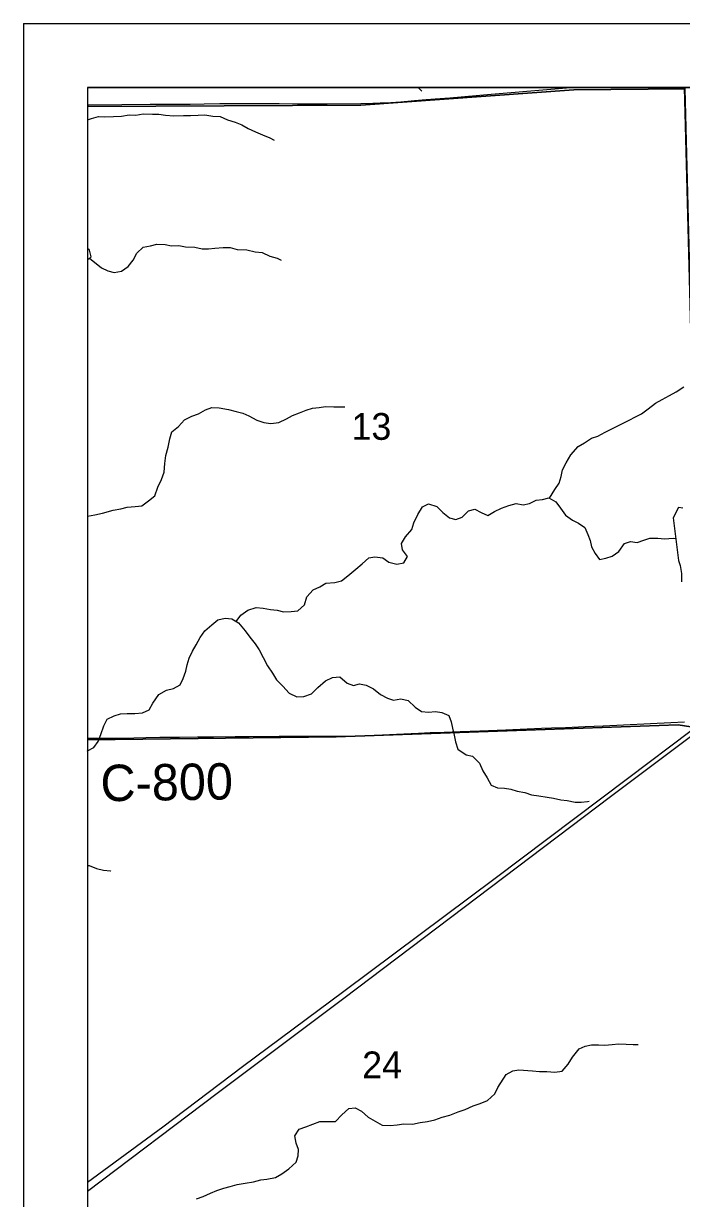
# Model space of a CAD drawing. Extents: x 0 to 34, y 0 to 22.
# Drawn here: x 2 to 3.028, y 19.165 to 21 of the extents above; entities that cross this region are included whole.
import ezdxf

# ---------------------------------------------------------------- set-up
doc = ezdxf.new("R2010")
doc.units = 0
for name, color, linetype in [('Default', 7, 'Continuous'), ('GM_X_County_Road', 7, 'Continuous'), ('GM_X_County_Road_Text', 7, 'Continuous'), ('GM_X_Interstate_Route', 7, 'Continuous'), ('GM_X_Minor_Lake', 7, 'Continuous'), ('GM_X_Minor_River', 7, 'Continuous'), ('GM_X_Rail_Line', 7, 'Continuous'), ('GM_X_Section_Text', 7, 'Continuous'), ('GM_X_Township_Road', 7, 'Continuous'), ('SH_Cut_Line', 7, 'Continuous'), ('SH_Data', 7, 'Continuous')]:
    doc.layers.add(name, color=color, linetype=linetype)

msp = doc.modelspace()

# ---------------------------------------------------------------- linework, layer by layer
at = {"layer": 'Default'}
for points in [[(3.0341, 20.9), (2.1, 20.9), (2.1, 20.8702), (2.5271, 20.8724), (2.8601, 20.8963), (3.0341, 20.898)], [(2.1, 20.8702), (2.1, 19.8813), (2.4888, 19.8857), (3.0228, 19.9046), (3.0592, 19.8987), (3.0341, 20.898), (2.8601, 20.8963), (2.5271, 20.8724)], [(2.1, 19.8813), (2.1, 18.8733), (3.073, 18.8909), (3.0592, 19.8987), (3.0228, 19.9046), (2.4888, 19.8857)]]:
    msp.add_lwpolyline(points, close=True, dxfattribs=at)
at = {"layer": 'GM_X_County_Road'}
msp.add_lwpolyline([(2.1, 19.8836), (2.1323, 19.8836), (2.1448, 19.8839), (2.1726, 19.8844), (2.1912, 19.8848), (2.213, 19.8852), (2.244, 19.8854), (2.272, 19.8857), (2.2968, 19.8859), (2.331, 19.8862), (2.3528, 19.8864), (2.3994, 19.8868), (2.4243, 19.8869), (2.4678, 19.887), (2.4989, 19.8866), (2.5176, 19.8867), (2.5331, 19.8874), (2.5611, 19.889), (2.5828, 19.89), (2.617, 19.8915), (2.6356, 19.8925), (2.6573, 19.8932), (2.6822, 19.894), (2.7133, 19.8951), (2.7536, 19.8968), (2.8095, 19.8992), (2.825, 19.8998), (2.8467, 19.9005), (2.8778, 19.9018), (2.9058, 19.903), (3.0114, 19.908), (3.0331, 19.909)], dxfattribs=at)
at = {"layer": 'GM_X_Interstate_Route'}
msp.add_lwpolyline([(3.0331, 20.9), (2.1, 20.9), (2.1, 16.8784), (2.6014, 16.878), (3.0939, 16.8719), (3.0724, 18.2926), (3.0747, 18.8969), (3.067, 19.3838), (3.0588, 19.9042)], close=True, dxfattribs=at)
at = {"layer": 'GM_X_Minor_Lake'}
for points in [[(2.1056, 20.6357), (2.1031, 20.646), (2.1, 20.6486)], [(2.1, 20.6315), (2.1017, 20.6323), (2.1041, 20.6339), (2.1056, 20.6357)]]:
    msp.add_lwpolyline(points, dxfattribs=at)
at = {"layer": 'GM_X_Minor_River'}
for points in [[(2.6166, 20.9), (2.6168, 20.8998), (2.6224, 20.8944)], [(2.1, 20.8493), (2.1063, 20.8516), (2.1173, 20.8549), (2.1272, 20.8544), (2.1404, 20.8547), (2.1533, 20.8553), (2.1651, 20.8571), (2.1753, 20.857), (2.1871, 20.8588), (2.2014, 20.8586), (2.2117, 20.8582), (2.2219, 20.8569), (2.2347, 20.8557), (2.2499, 20.8563), (2.2609, 20.8562), (2.273, 20.8568), (2.2836, 20.8571), (2.2957, 20.8551), (2.3074, 20.8546), (2.3187, 20.8495), (2.3308, 20.8456), (2.341, 20.8417), (2.3512, 20.8359), (2.3625, 20.8309), (2.3735, 20.8262), (2.3848, 20.8212), (2.3919, 20.8177)], [(2.1034, 20.6334), (2.1218, 20.6185), (2.132, 20.6138), (2.1418, 20.6111), (2.1532, 20.6129), (2.1634, 20.6203), (2.1715, 20.6305), (2.1769, 20.6411), (2.1872, 20.6505), (2.1982, 20.6526), (2.2084, 20.6552), (2.2213, 20.6547), (2.2315, 20.6527), (2.2429, 20.653), (2.2534, 20.651), (2.2675, 20.6508), (2.2792, 20.6481), (2.289, 20.648), (2.2989, 20.649), (2.3121, 20.65), (2.3231, 20.6499), (2.3341, 20.6471), (2.3488, 20.6462), (2.3621, 20.6431), (2.373, 20.6422), (2.3851, 20.6364), (2.3964, 20.6336), (2.4028, 20.6302)], [(2.8218, 20.2586), (2.83, 20.272), (2.8372, 20.2818), (2.84, 20.2924), (2.842, 20.303), (2.8477, 20.314), (2.855, 20.3264), (2.8665, 20.3392), (2.8764, 20.3452), (2.8874, 20.3523), (2.8973, 20.3552), (2.9091, 20.3619), (2.9224, 20.3686), (2.9331, 20.3735), (2.9464, 20.3805), (2.9563, 20.3854), (2.9658, 20.3902), (2.9761, 20.3981), (2.9875, 20.4067), (2.9982, 20.4127), (3.0092, 20.419), (3.0198, 20.4246), (3.0316, 20.4325)], [(2.1, 20.2305), (2.1117, 20.2323), (2.1234, 20.2352), (2.1401, 20.2396), (2.1519, 20.2418), (2.1618, 20.2444), (2.1743, 20.2454), (2.1849, 20.2468), (2.1952, 20.2543), (2.2051, 20.2621), (2.2101, 20.2758), (2.2159, 20.2875), (2.2198, 20.2992), (2.221, 20.3128), (2.2223, 20.325), (2.2258, 20.3382), (2.2286, 20.3511), (2.2317, 20.3621), (2.242, 20.3707), (2.2515, 20.3808), (2.2629, 20.3868), (2.2736, 20.3905), (2.2842, 20.3968), (2.2941, 20.4001), (2.3058, 20.3997), (2.3202, 20.3969), (2.3323, 20.3937), (2.3425, 20.3913), (2.3523, 20.3871), (2.3644, 20.3805), (2.3753, 20.377), (2.3867, 20.3753), (2.3988, 20.3767), (2.411, 20.3823), (2.4205, 20.3879), (2.4311, 20.3916), (2.4418, 20.3961), (2.4516, 20.399), (2.4622, 20.4004), (2.4717, 20.4015), (2.485, 20.401), (2.4959, 20.4012), (2.502, 20.4012)], [(2.3321, 20.066), (2.3398, 20.0757), (2.3505, 20.0836), (2.3634, 20.0876), (2.3744, 20.0867), (2.3861, 20.0847), (2.3963, 20.0839), (2.4061, 20.0811), (2.4182, 20.0818), (2.4285, 20.0824), (2.4392, 20.0918), (2.4427, 20.1047), (2.4526, 20.1152), (2.4629, 20.12), (2.4724, 20.1256), (2.4864, 20.127), (2.497, 20.1296), (2.507, 20.1374), (2.5195, 20.1476), (2.5291, 20.1562), (2.5394, 20.1656), (2.5492, 20.167), (2.5613, 20.1654), (2.5711, 20.1584), (2.5832, 20.1557), (2.5942, 20.1575), (2.6, 20.1676), (2.5921, 20.178), (2.5907, 20.1878), (2.5968, 20.198), (2.6068, 20.2097), (2.6099, 20.2199), (2.6164, 20.2331), (2.6234, 20.2448), (2.6329, 20.2497), (2.6457, 20.2457), (2.6551, 20.2362), (2.6656, 20.2277), (2.6755, 20.2253), (2.6857, 20.229), (2.6953, 20.2388), (2.7051, 20.2414), (2.7153, 20.236), (2.7255, 20.2313), (2.7361, 20.238), (2.7468, 20.2429), (2.7586, 20.2469), (2.7696, 20.2502), (2.7809, 20.2482), (2.7908, 20.2504), (2.801, 20.2552), (2.8109, 20.2563), (2.8208, 20.2592), (2.8317, 20.2527), (2.8392, 20.2427), (2.847, 20.232), (2.8576, 20.2243), (2.8674, 20.2197), (2.8772, 20.2128), (2.882, 20.2017), (2.8853, 20.1922), (2.8875, 20.1827), (2.8931, 20.1724), (2.8998, 20.1628), (2.9101, 20.165), (2.9196, 20.168), (2.9302, 20.1754), (2.9391, 20.1879), (2.9486, 20.1908), (2.9588, 20.1892), (2.9694, 20.1929), (2.9789, 20.1962), (2.991, 20.1961), (3.0016, 20.1952), (3.0149, 20.1959), (3.0191, 20.1956)], [(3.03, 20.2431), (3.0236, 20.244), (3.0151, 20.2281)], [(3.0151, 20.2281), (3.0233, 20.1613)], [(3.0233, 20.1613), (3.0262, 20.1533), (3.028, 20.1407), (3.0283, 20.1278)], [(2.1, 19.8636), (2.1002, 19.8637), (2.1101, 19.8689), (2.1166, 19.8787), (2.1209, 19.8896), (2.1255, 19.9029), (2.1309, 19.9135), (2.1416, 19.9187), (2.1518, 19.9216), (2.162, 19.9223), (2.1738, 19.9225), (2.1859, 19.9232), (2.1962, 19.928), (2.2023, 19.9382), (2.2115, 19.9517), (2.2237, 19.9588), (2.2343, 19.9614), (2.245, 19.967), (2.2496, 19.9768), (2.2539, 19.9885), (2.2555, 19.9984), (2.259, 20.0086), (2.264, 20.0195), (2.2697, 20.0293), (2.2759, 20.0407), (2.2836, 20.0512), (2.2942, 20.0606), (2.3038, 20.0688), (2.3152, 20.0714), (2.3258, 20.0701), (2.3359, 20.0636), (2.3464, 20.0513), (2.3535, 20.0414), (2.3622, 20.0311), (2.3681, 20.0215), (2.3745, 20.0097), (2.3812, 19.9968), (2.389, 19.9853), (2.3954, 19.9746), (2.4051, 19.965), (2.4149, 19.9539), (2.427, 19.9481), (2.4379, 19.9488), (2.4501, 19.9532), (2.46, 19.963), (2.4719, 19.9731), (2.4829, 19.9787), (2.4942, 19.9797), (2.5055, 19.9698), (2.5157, 19.9662), (2.5252, 19.9684), (2.5354, 19.9664), (2.5471, 19.9606), (2.5576, 19.9518), (2.5686, 19.9464), (2.5784, 19.9433), (2.5894, 19.945), (2.6011, 19.9427), (2.612, 19.9319), (2.6218, 19.9254)], [(2.6218, 19.9254), (2.6327, 19.9245), (2.6437, 19.9255), (2.6536, 19.9239), (2.6645, 19.9189), (2.6682, 19.9094), (2.6704, 19.8991), (2.673, 19.8885), (2.6751, 19.8778), (2.6788, 19.8664), (2.6916, 19.8579), (2.7018, 19.8556), (2.7123, 19.8448), (2.7175, 19.8326), (2.7246, 19.8216), (2.731, 19.8105), (2.7408, 19.8062), (2.7518, 19.8054), (2.7616, 19.8041), (2.7714, 19.801), (2.7835, 19.7986), (2.7937, 19.7951), (2.8054, 19.7935), (2.8183, 19.7915), (2.8281, 19.7902), (2.8398, 19.7875), (2.8497, 19.7862), (2.8618, 19.7838), (2.8716, 19.7837), (2.8811, 19.7848), (2.8837, 19.7851)], [(2.1, 19.6847), (2.1028, 19.6846), (2.1142, 19.6803), (2.1251, 19.6775), (2.1357, 19.6763), (2.1353, 19.6756)], [(2.7363, 19.3283), (2.7413, 19.3381), (2.7544, 19.3585), (2.7647, 19.3641), (2.7741, 19.3655), (2.7953, 19.3642), (2.8063, 19.3629), (2.8177, 19.3632), (2.8302, 19.3623), (2.8419, 19.3637), (2.8511, 19.3746), (2.8576, 19.3856), (2.868, 19.3987), (2.8778, 19.4024), (2.8877, 19.4046), (2.8987, 19.4049), (2.9085, 19.4044), (2.9199, 19.4051), (2.9297, 19.4061), (2.9415, 19.4056), (2.9524, 19.4051), (2.9604, 19.4054)], [(2.2703, 19.164), (2.2809, 19.1681), (2.2923, 19.1733), (2.3022, 19.1774), (2.3132, 19.1807), (2.3227, 19.1836), (2.3341, 19.1866), (2.3466, 19.1887), (2.3595, 19.1909), (2.3709, 19.1938), (2.3804, 19.1948), (2.3937, 19.1977), (2.4035, 19.2033), (2.4146, 19.2112), (2.426, 19.2213), (2.4292, 19.2315), (2.4296, 19.241), (2.4259, 19.2513), (2.4241, 19.2627), (2.4307, 19.2732), (2.4413, 19.2769), (2.4523, 19.2806), (2.4629, 19.2851), (2.4758, 19.2849), (2.4876, 19.2852), (2.4975, 19.2954), (2.5082, 19.3055), (2.5184, 19.3062), (2.5282, 19.3011), (2.5384, 19.2919), (2.5493, 19.2854), (2.5606, 19.2792), (2.5727, 19.2787), (2.5841, 19.2797), (2.5943, 19.2811), (2.6076, 19.281), (2.6197, 19.2832), (2.6314, 19.285), (2.6425, 19.2875), (2.6542, 19.2916), (2.6664, 19.2949), (2.6793, 19.3), (2.6899, 19.3037), (2.7025, 19.3093), (2.7135, 19.313), (2.7249, 19.3178), (2.7363, 19.3283)]]:
    msp.add_lwpolyline(points, dxfattribs=at)
at = {"layer": 'GM_X_Rail_Line'}
for points in [[(2.1, 19.1903), (2.2176, 19.2766), (2.3422, 19.3707), (2.5003, 19.4885), (2.7369, 19.665), (2.944, 19.8207), (3.3415, 20.1206), (3.4596, 20.2081), (3.5596, 20.3194), (3.7554, 20.3776), (3.8584, 20.4014), (3.9589, 20.4196), (4.0414, 20.4251), (4.3012, 20.4183), (4.3584, 20.4251), (4.4262, 20.4416), (4.5028, 20.4697), (4.9465, 20.6634), (5.0176, 20.7062), (5.0741, 20.7492), (5.1326, 20.8127), (5.1783, 20.8803), (5.1912, 20.9)], [(2.1, 19.1763), (2.3025, 19.329), (2.5005, 19.4778), (2.9171, 19.7925), (3.0629, 19.9022), (3.3144, 20.0919), (3.4796, 20.2167), (3.5208, 20.2463), (3.5593, 20.2719), (3.6039, 20.2977), (3.6372, 20.3142), (3.6622, 20.326), (3.7035, 20.3435), (3.7526, 20.3598), (3.7901, 20.3703), (3.8195, 20.3771), (3.8669, 20.3851), (3.934, 20.3918), (3.9658, 20.3929), (3.9898, 20.3929), (4.0344, 20.3908)]]:
    msp.add_lwpolyline(points, dxfattribs=at)
at = {"layer": 'GM_X_Township_Road'}
msp.add_lwpolyline([(2.1, 20.8729), (2.1017, 20.8729), (2.1539, 20.8734), (2.198, 20.8739), (2.2348, 20.874), (2.2602, 20.8741), (2.2821, 20.8747), (2.3068, 20.8749), (2.3379, 20.8751), (2.3749, 20.875), (2.3997, 20.8748), (2.4279, 20.8745), (2.4432, 20.8746), (2.4745, 20.8746), (2.5273, 20.875), (2.546, 20.8753), (2.5572, 20.876), (2.5739, 20.8768), (2.5895, 20.8777), (2.6112, 20.8797), (2.6294, 20.8812), (2.6432, 20.8824), (2.6663, 20.8841), (2.7306, 20.8894), (2.8179, 20.8968), (2.8548, 20.9)], dxfattribs=at)
at = {"layer": 'SH_Cut_Line'}
msp.add_lwpolyline([(8.1285, 16.8707), (8.1148, 17.8694), (8.0976, 18.2853), (8.0958, 18.3144), (8.0817, 18.88), (8.0959, 19.2713), (8.1023, 19.3817), (8.0929, 19.6339), (8.0678, 20.8562), (8.0675, 20.8733), (8.067, 20.8954), (8.0669, 20.9), (2.1, 20.9), (2.1, 14.1)], dxfattribs=at)
at = {"layer": 'SH_Data'}
for p, q in [((2, 21), (9, 21)), ((2, 21), (2, 14)), ((2.1, 20.9), (2.1, 14.1)), ((2.1, 20.9), (8.9, 20.9))]:
    msp.add_line(p, q, dxfattribs=at)

# ---------------------------------------------------------------- texts
at = {"layer": 'GM_X_County_Road_Text'}
msp.add_text('C-800', height=0.05682, rotation=0.8261, dxfattribs=at).set_placement((2.1207, 19.7851))
at = {"layer": 'GM_X_Section_Text'}
for s, p in [('13', (2.5125, 20.3497)), ('24', (2.5292, 19.3525))]:
    msp.add_text(s, height=0.04186, rotation=0, dxfattribs=at).set_placement(p)

doc.saveas('drawing.dxf')
